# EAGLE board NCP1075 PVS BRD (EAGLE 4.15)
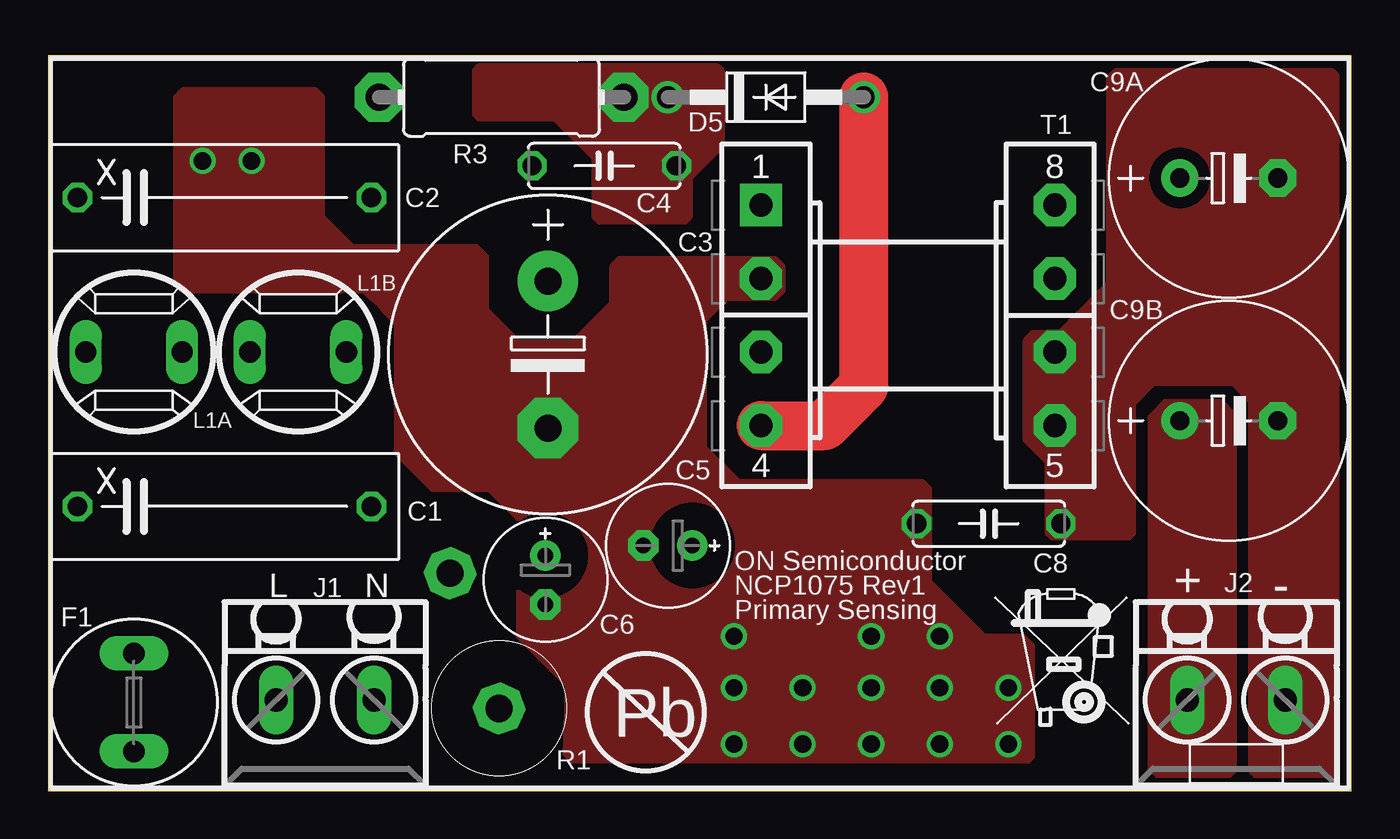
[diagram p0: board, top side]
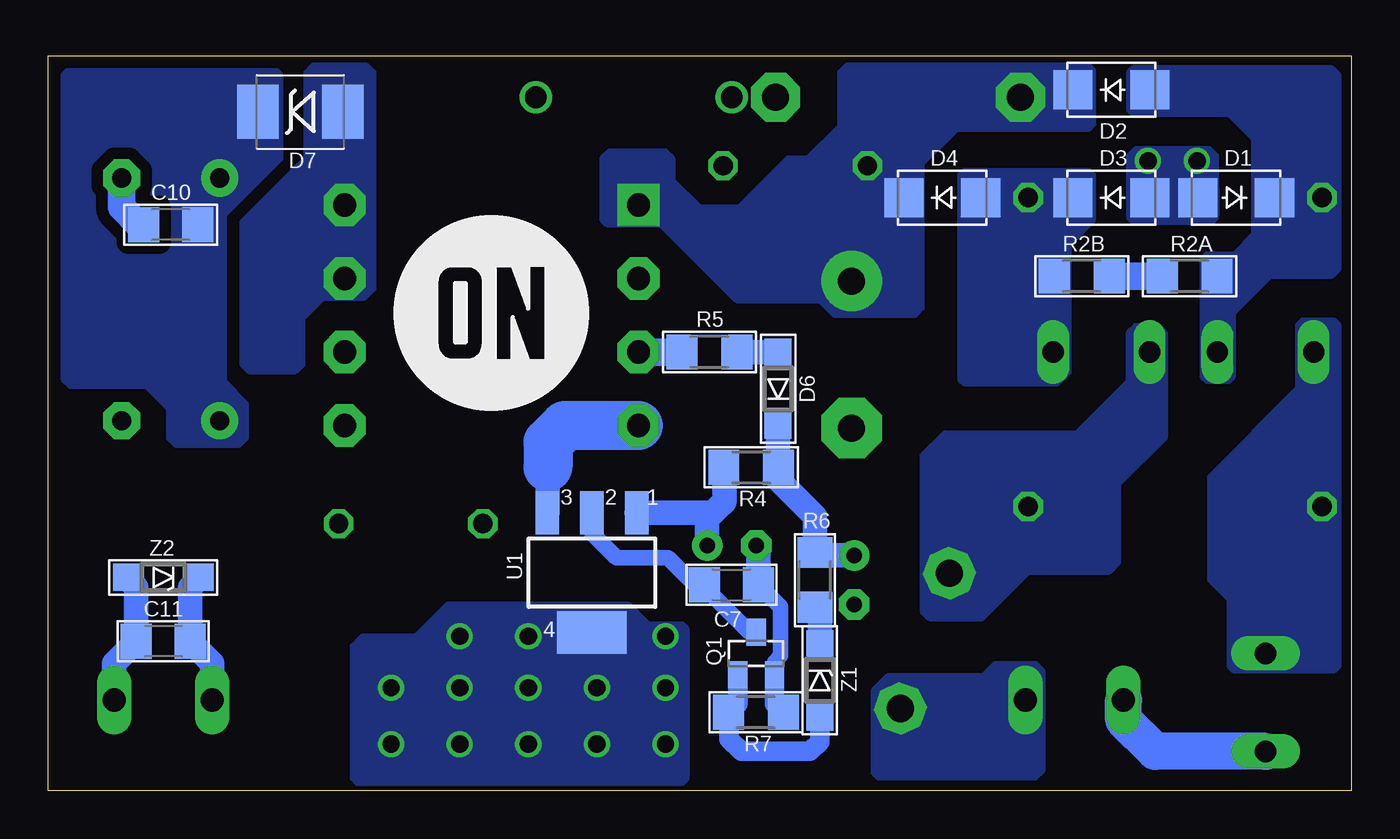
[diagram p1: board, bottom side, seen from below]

Size 67.56 x 38.1 mm. Coordinates in mm from the lower left corner, seen from the top.
Outline: 0,0 67.56,0 67.56,38.1 0,38.1 0,0
Copper layers (1*16): Top 0.035mm / dielectric 1.5mm / Bottom 0.035mm
Design rules "default": minimum track width 10mil, minimum drill 19mil, track to track 8mil, track to pad 8mil, pad to pad 8mil, via to via 8mil, smd to smd 8mil, copper to edge 5mil, drill to drill 8mil, minimum pad ring 10mil, minimum via ring 8mil, stop-mask expansion 4mil, vias tented up to drill 0mil, thermal gap 10mil

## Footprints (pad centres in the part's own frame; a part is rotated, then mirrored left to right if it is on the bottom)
XC17.5B5.5-LS15 = drill 1.016 octagon: 1 -7.62,0; 2 7.62,0
E7,5-16 = drill 1.4 pad 3.15 round: + -3.81,0 | drill 1.4 pad 3.15 octagon: - 3.81,0
C075-025X080 = drill 1 octagon: 1 -3.74,0; 2 3.74,0
E2.5-6.5 = drill 0.813 pad 1.575 round: + -1.27,0 | drill 0.813 pad 1.575 octagon: - 1.27,0
C1206 = smd 1.6 x 1.8: 1 -1.4,0; 2 1.4,0
E5-12,5 = drill 1 pad 1.93 round: + -2.54,0 | drill 1 pad 1.93 octagon: - 2.54,0
SMA-DIODE = smd 2.032 x 2.032: A 1.994,0; C -1.994,0
DO41-10 = drill 1.118 round: A 5.08,0; C -5.08,0
SOD123 = smd 1.4 x 1.4: A 1.9,0; C -1.9,0
SMB_SCHOTTKEY = smd 2.159 x 2.794: A 2.2,0; C -2.2,0
TR5 = drill 1.1 pad 1.778 long: 1 -2.54,0; 2 2.54,0
2-PIN = drill 1.2 long: + -2.54,0; - 2.54,0
WE-7447728215 = drill 1.1 long: P$1 -2.5,0; P$2 2.5,0
SOT23-BEC = smd 1 x 1.4: B -0.95,-1.1; C 0,1.1; E 0.95,-1.1
3W-STAND-UP = drill 1.4 pad 2.54 octagon: P$1 3.75,0; P$2 -3.71,0
R1206 = smd 1.6 x 1.803: 1 -1.422,0; 2 1.422,0
0411/12 = drill 1.4 pad 2.54 octagon: 1 -6.35,0; 2 6.35,0
E_16/8/5-EF_16-HORIZONTAL = drill 1.2 pad 2.184 square: 1 -7.62,5.715 | drill 1.2 pad 2.184 octagon: 2 -7.62,1.905; 3 -7.62,-1.905; 4 -7.62,-5.715; 5 7.62,-5.715; 6 7.62,-1.905; 7 7.62,1.905; 8 7.62,5.715
SOT-223 = smd 1.219 x 2.235: 1 -2.311,-3.099; 2 0,-3.099; 3 2.311,-3.099 | smd 3.6 x 2.2: 4 0,3.099
SOD123-ZENER = smd 1.4 x 1.4: A 1.9,0; C -1.9,0

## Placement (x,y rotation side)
C1  100nF  [XC17.5B5.5-LS15]  9.14,14.73 0 top
C2  100nF  [XC17.5B5.5-LS15]  9.14,30.73 0 top
C3  22uF  [E7,5-16]  25.91,22.61 270 top
C4  1nF  [C075-025X080]  28.83,32.39 0 top
C5  22uF  [E2.5-6.5]  32.13,12.7 180 top
C6  22uF  [E2.5-6.5]  25.78,10.92 270 top
C7  1nF  [C1206]  32.13,10.67 0 bottom
C8  1nF  [C075-025X080]  48.77,13.84 0 top
C9A  1000uF  [E5-12,5]  61.21,31.75 0 top
C9B  1000uF  [E5-12,5]  61.21,19.18 0 top
C10  100nF  [C1206]  61.21,29.34 180 bottom
C11  100nF  [C1206]  61.6,7.75 180 bottom
D1  MRA4007  [SMA-DIODE]  5.97,30.73 180 bottom
D2  MRA4007  [SMA-DIODE]  12.45,36.32 0 bottom
D3  MRA4007  [SMA-DIODE]  12.45,30.73 0 bottom
D4  MRA4007  [SMA-DIODE]  21.21,30.73 0 bottom
D5  1N4937  [DO41-10]  37.21,35.94 0 top
D6  MMSD4148A  [SOD123]  29.72,20.83 90 bottom
D7  MBRS260T3  [SMB_SCHOTTKEY]  54.48,35.18 0 bottom
E$2  [ON2]  44.58,24.77 0 bottom
F1  1.5A  [TR5]  4.45,4.57 90 top
J1  [2-PIN]  14.35,4.7 0 top
J2  [2-PIN]  61.6,4.7 0 top
L1A  1mH  [WE-7447728215]  4.45,22.73 0 top
L1B  1mH  [WE-7447728215]  12.95,22.73 0 top
Q1  MMBTA06  [SOT23-BEC]  30.86,7.11 0 bottom
R1  4.7/3W  [3W-STAND-UP]  22.12,7.74 110 top
R2A  3.3M  [R1206]  8.38,26.67 0 bottom
R2B  3.3M  [R1206]  13.97,26.67 0 bottom
R3  68K  [0411/12]  23.5,35.94 180 top
R4  1K  [R1206]  31.12,16.76 180 bottom
R5  22  [R1206]  33.27,22.73 0 bottom
R6  47  [R1206]  27.81,10.92 270 bottom
R7  680  [R1206]  30.86,4.06 0 bottom
T1  [E_16/8/5-EF_16-HORIZONTAL]  44.58,24.64 0 top
U1  NCP1075  [SOT-223]  39.37,11.3 180 bottom
U$3  [WEEE_SMALL]  52.71,4.7 0 top
Z1  MMSZ5241B  [SOD123-ZENER]  27.56,5.72 270 bottom
Z2  MMSZ5245B  [SOD123-ZENER]  61.6,11.05 180 bottom

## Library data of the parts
C1-C8 C9A C9B C10 C11 R2A R2B R3-R7 = rcl
D1-D7 Z1 Z2 = diode
E$2 = loga
F1 = fuse
J1 J2 = My CONNECTOR lib
L1A L1B = MY  INDUCTOR Lib
Q1 = transistor-npn
R1 = resistor-power
T1 = My X-former
U1 = My IC Lib
U$3 = My Sign Lib

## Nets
N$1: C1.1 F1.2 L1A.P$1
N$2: F1.1 J1.+
N$3: C2.1 D1.C D2.A L1A.P$2 R2A.2
N$4: C1.2 L1B.P$1 R1.P$1
N$5: J1.- R1.P$2
N$6: C2.2 D3.C D4.A L1B.P$2 R2B.1
N$7: R2A.1 R2B.2
N$9: D5.A T1.4 U1.3
N$10: C3.+ C4.1 D2.C D4.C R3.2 T1.1
N$11: C4.2 D5.C R3.1
N$12: R6.2 Z1.C
N$13: C5.+ R4.2 U1.1
N$14: Q1.B R7.1 Z1.A
N$18: R5.1 T1.3
N$19: D6.A R5.2
N$20: C6.+ D6.C R4.1 R6.1
N$21: C7.1 Q1.C U1.2
N$25: D7.A T1.7 T1.8
N$28: C8.2 C9A.- C9B.- C10.2 C11.2 J2.- T1.5 T1.6 Z2.A
N$30: C9A.+ C9B.+ C10.1 C11.1 D7.C J2.+ Z2.C
N$44: C3.- C5.- C6.- C7.2 C8.1 D1.A D3.A Q1.E R7.2 T1.2 U1.4

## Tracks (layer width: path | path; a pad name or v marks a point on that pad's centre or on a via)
N$1
  pour Bottom (no thermals): 6.35,9.91 6.35,6.48 6.1,6.22 0.89,6.22 0.64,6.48 0.64,24.13 0.89,24.38 2.54,24.38 2.79,24.13 2.79,20.83 7.37,16.26 7.37,10.92
N$2
  Bottom 1.93: F1.1 10.16,2.03 11.81,3.68 J1.+
N$3
  pour Bottom (no thermals): 6.1,21.46 6.1,24.77 4.19,26.67 1.02,26.67 0.64,27.05 0.64,37.08 1.02,37.47 11.3,37.47 11.56,37.21 11.56,35.31 11.3,35.05 6.35,35.05 5.08,33.78 5.08,28.83 6.1,27.81 7.49,27.81 7.75,27.56 7.75,21.46 7.49,21.21 6.35,21.21
N$4
  pour Bottom (no thermals): 16.76,11.3 19.18,8.89 21.84,8.89 22.23,9.27 22.23,17.4 21.08,18.54 14.22,18.54 11.56,21.21 11.56,23.75 11.18,24.13 10.03,24.13 9.65,23.75 9.65,18.29 12.07,15.88 12.07,11.81 12.57,11.3
N$5
  pour Bottom (no thermals): 16,6.22 16,1.02 16.38,0.64 24.51,0.64 24.77,0.89 24.77,5.21 24,5.97 19.05,5.97 18.42,6.6 16.38,6.6
N$6
  pour Bottom (no thermals): 14.61,22.73 14.61,28.32 13.34,29.59 13.34,31.88 13.59,32.13 20.07,32.13 20.32,31.88 20.32,21.34 20.07,21.08 15.24,21.08 14.61,21.72
N$7
  Bottom 1.422: R2A.1 R2B.2
N$9
  Top 2.54: D5.A 42.29,20.96 40.26,18.92 T1.4
  Bottom 1.27: U1.3 41.68,16.74 41.66,16.76
  Bottom 2.54: 41.66,16.76 41.66,18.03 40.77,18.92 T1.4
N$10
  pour Bottom (no thermals): 13.59,37.59 26.16,37.59 26.54,37.21 26.54,34.42 28.19,32.77 29.21,32.77 31.75,30.23 33.78,30.23 35.18,31.62 35.18,32.77 35.56,33.15 38.48,33.15 38.86,32.77 38.86,29.59 38.61,29.34 35.81,29.34 31.88,25.4 27.56,25.4 26.8,24.64 22.61,24.64 22.23,25.02 22.23,32.51 20.45,34.29 13.59,34.29 13.34,34.54 13.34,37.34
N$11
  pour Top (no thermals): 22.35,37.59 34.67,37.59 34.93,37.34 34.93,33.4 33.27,31.75 33.27,29.72 33.02,29.46 28.58,29.46 28.32,29.72 28.32,32.77 26.29,34.8 22.35,34.8 22.1,35.05 22.1,37.34
N$12
  Bottom 1.27: R6.2 27.81,9.53 27.56,9.27 Z1.C
N$13
  Bottom 1.27: U1.1 33.1,14.4 32.89,14.61 | 32.89,14.61 32.51,14.99 32.51,16.64 32.54,16.66 R4.2 | C5.+ 33.4,14.1 32.89,14.61
N$14
  Bottom 1.016: Z1.A 27.56,2.54 28.07,2.03 31.62,2.03 32.26,2.67 32.26,4.06 | 32.26,4.06 R7.1 | Q1.B 31.81,4.51 32.26,4.06
N$18
  Bottom 1.422: R5.1 T1.3
N$19
  Bottom 1.27: D6.A R5.2
N$20
  Bottom 1.27: D6.C 29.72,16.79 R4.1 29.72,16.76 29.72,16.13 27.81,14.22 R6.1 27.81,12.32 27.69,12.19 C6.+
N$21
  Bottom 0.813: U1.2 39.37,13.34 38.1,12.07 35.43,12.07 34.04,10.67 C7.1 33.53,10.54 31.2,8.21 Q1.C
N$25
  pour Bottom (no thermals): 50.67,26.04 50.67,37.21 51.05,37.59 53.85,37.59 54.23,37.21 54.23,32.77 57.53,29.46 57.53,22.1 57.15,21.72 54.74,21.72 54.36,22.1 54.36,24.51 53.34,25.53 51.18,25.53
N$28
  Bottom 1.27: J2.- 64.14,6.6 C11.2 63,10.54 Z2.A
  Bottom 1.422: C10.2 62.87,29.34 63.75,30.23 C9A.-
  pour Top (isolate 0.61, no thermals): 50.67,23.37 51.05,23.75 52.45,23.75 54.99,26.29 54.99,36.96 55.37,37.34 66.55,37.34 66.8,37.08 66.8,1.02 66.55,0.76 62.61,0.76 62.36,1.02 62.36,20.19 61.47,21.08 57.28,21.08 56.26,20.07 56.26,13.34 56.01,13.08 52.07,13.08 51.82,13.34 51.82,17.02 50.67,18.16
N$30
  Bottom 1.27: J2.+ 59.06,6.6 C11.1 60.2,10.54 Z2.C
  pour Bottom (isolate 0.61, no thermals): 55.75,37.34 66.55,37.34 66.8,37.08 66.8,21.34 66.42,20.96 62.48,20.96 61.34,19.81 61.34,18.29 60.96,17.91 57.66,17.91 57.28,18.29 57.28,20.07 58.42,21.21 58.42,29.85 55.5,32.77 55.5,37.08
  pour Top (isolate 0.61, rank 2, no thermals): 61.21,0.76 57.53,0.76 57.15,1.14 57.15,19.81 57.53,20.19 61.09,20.19 61.47,19.81 61.47,1.02
N$44  (via drill 0.9)
  Bottom 0.813: Q1.E 29.91,6.67 29.59,6.99 29.59,9.53 C7.2
  Bottom 1.016: R7.2 29.46,4.06 29.91,4.51 Q1.E
  Bottom 1.27: C7.2 30.73,12.57 C5.-
  other vias: 8,32.64 10.54,32.64 46.23,2.41 42.67,5.33 46.23,5.33 42.67,2.41 39.12,2.41 39.12,5.33 35.56,2.41 49.78,5.33 35.56,5.33 49.78,2.41 35.56,8 42.67,8 46.23,8
  pour Bottom (no thermals): 6.99,29.85 6.99,32.89 7.37,33.27 11.18,33.27 11.56,32.89 11.56,29.72 11.3,29.46 7.24,29.46 6.99,29.72 6.99,31.24
  pour Bottom (no thermals): 34.67,8.64 36.45,8.64 37.47,9.65 46.86,9.65 48.51,8 51.31,8 51.82,7.49 51.82,0.64 51.56,0.38 34.67,0.38 34.42,0.64 34.42,8.38
  pour Top (isolate 1.422, no thermals): 6.6,35.94 6.6,26.29 6.99,25.91 16.38,25.91 18.03,24.26 18.03,17.53 19.94,15.62 22.86,15.62 24.38,14.1 24.38,8 26.92,5.46 26.8,1.91 27.18,1.52 50.8,1.52 51.05,1.78 51.05,7.49 50.55,8 48.51,8 45.72,10.8 45.72,15.62 45.34,16 35.81,16 34.04,17.78 34.04,24.38 35.18,25.53 37.72,25.53 38.1,25.91 38.1,27.18 37.72,27.56 29.59,27.56 29.21,27.18 29.21,25.27 27.18,23.24 24.38,23.24 22.73,24.89 22.73,27.69 22.23,28.19 15.75,28.19 14.22,29.72 14.22,35.94 13.84,36.32 6.99,36.32

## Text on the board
tPlace: ON Semiconductor | L | N | NCP1075 Rev1 | + | - | Primary Sensing | Pb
